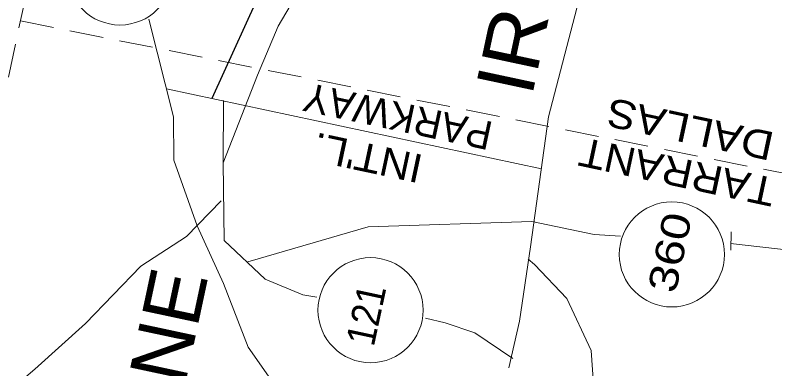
# Model space of a CAD drawing. Extents: x 2363411 to 2369126, y 6976878 to 6988319.
# Drawn here: x 2365843.9 to 2365979.2, y 6977238.8 to 6977301.9 of the extents above; entities that cross this region are included whole.
import ezdxf

# ---------------------------------------------------------------- set-up
doc = ezdxf.new("R2010")
doc.units = 0
doc.header["$LTSCALE"] = 2
doc.linetypes.add('MEDIUM_DASHED', pattern=[4.5, 3, -1.5])
doc.layers.add('62', color=7, linetype='Continuous', lineweight=13)
doc.layers.add('63', color=7, linetype='Continuous', lineweight=13)

msp = doc.modelspace()

# ---------------------------------------------------------------- linework, layer by layer
at = {"layer": '62', "linetype": 'MEDIUM_DASHED'}
for p, q in [((2365864.629, 6977393.47), (2365770.962, 6976955.102)), ((2365844.834, 6977300.827), (2366120.392, 6977245.768))]:
    msp.add_line(p, q, dxfattribs=at)
at = {"layer": '62'}
for p, q in [((2365937.638, 6977274.464), (2365870.829, 6977288.739)), ((2365880.938, 6977275.533), (2365880.992, 6977286.661)), ((2365874.425, 6977262.384), (2365880.614, 6977268.745)), ((2365935.934, 6977265.095), (2365947.026, 6977262.727)), ((2365947.026, 6977262.727), (2365951.756, 6977262.473)), ((2365971.404, 6977259.979), (2365971.456, 6977263.236)), ((2365983.687, 6977259.747), (2365971.313, 6977261.17)), ((2365936.413, 6977257.422), (2365935.278, 6977258.356)), ((2365895.124, 6977252.002), (2365897.618, 6977251.608)), ((2365920.523, 6977247.035), (2365916.971, 6977247.863)), ((2365933.745, 6977247.316), (2365931.81, 6977239.009)), ((2365885.393, 6977242.646), (2365892.097, 6977233.203))]:
    msp.add_line(p, q, dxfattribs=at)
for points in [[(2365933.745, 6977247.316), (2365935.719, 6977260.537), (2365938.925, 6977283.713), (2365944.32, 6977304.446), (2365947.999, 6977318.223), (2365951.965, 6977335.808), (2365951.701, 6977346.428), (2365947.185, 6977359.539), (2365943.374, 6977373.908), (2365943.087, 6977378.064)], [(2365887.078, 6977291.135), (2365890.75, 6977299.923), (2365897.513, 6977311.432), (2365905.681, 6977318.96)], [(2365876.303, 6977264.283), (2365872.175, 6977275.98), (2365872.104, 6977283.724), (2365867.682, 6977301.146)], [(2365881.155, 6977261.684), (2365880.938, 6977275.533), (2365887.078, 6977291.135)], [(2365876.303, 6977264.283), (2365881.03, 6977254), (2365885.393, 6977242.646)], [(2365935.934, 6977265.095), (2365906.78, 6977264.121), (2365885.362, 6977257.908)], [(2365745.602, 6977025.615), (2365742.995, 6977037.011), (2365744.177, 6977051.369), (2365754.758, 6977065.562), (2365757.967, 6977076.059), (2365767.656, 6977087.91), (2365774.215, 6977096.102), (2365778.852, 6977103.376), (2365783.338, 6977114.034), (2365786.122, 6977122.873), (2365789.101, 6977134.663), (2365791.544, 6977148.682), (2365797.575, 6977165.918), (2365800.831, 6977177.279), (2365805.2, 6977190.083), (2365814.728, 6977203.211), (2365824.115, 6977215.605), (2365833.318, 6977226.804), (2365847.376, 6977238.756), (2365856.409, 6977246.882), (2365866.274, 6977257.086), (2365874.425, 6977262.384)], [(2365895.124, 6977252.002), (2365888.401, 6977254.796), (2365881.155, 6977261.684)], [(2365947.455, 6977228.349), (2365946.525, 6977242.078), (2365942.171, 6977251.316), (2365936.413, 6977257.422)], [(2365932.577, 6977240.663), (2365925.797, 6977245.218), (2365920.523, 6977247.035)]]:
    msp.add_lwpolyline(points, dxfattribs=at)
at = {"layer": '62', "lineweight": 25}
msp.add_lwpolyline([(2365903.569, 6977335.148), (2365888.706, 6977308.551), (2365878.926, 6977287.009)], dxfattribs=at)
at = {"layer": '62'}
for centre in [(2365862.565, 6977309.461), (2365960.88, 6977259.201), (2365907.202, 6977249.263)]:
    msp.add_circle(centre, 9.364, dxfattribs=at)
at = {"layer": '63', "linetype": 'MEDIUM_DASHED'}
for p, q in [((2365864.629, 6977393.47), (2365770.962, 6976955.102)), ((2365844.834, 6977300.827), (2366120.392, 6977245.768))]:
    msp.add_line(p, q, dxfattribs=at)
at = {"layer": '63'}
for p, q in [((2365937.638, 6977274.464), (2365870.829, 6977288.739)), ((2365880.938, 6977275.533), (2365880.992, 6977286.661)), ((2365874.425, 6977262.384), (2365880.614, 6977268.745)), ((2365935.934, 6977265.095), (2365947.026, 6977262.727)), ((2365947.026, 6977262.727), (2365951.756, 6977262.473)), ((2365971.404, 6977259.979), (2365971.456, 6977263.236)), ((2365983.687, 6977259.747), (2365971.313, 6977261.17)), ((2365936.413, 6977257.422), (2365935.278, 6977258.356)), ((2365895.124, 6977252.002), (2365897.618, 6977251.608)), ((2365920.523, 6977247.035), (2365916.971, 6977247.863)), ((2365933.745, 6977247.316), (2365931.81, 6977239.009)), ((2365885.393, 6977242.646), (2365892.097, 6977233.203))]:
    msp.add_line(p, q, dxfattribs=at)
for points in [[(2365933.745, 6977247.316), (2365935.719, 6977260.537), (2365938.925, 6977283.713), (2365944.32, 6977304.446), (2365947.999, 6977318.223), (2365951.965, 6977335.808), (2365951.701, 6977346.428), (2365947.185, 6977359.539), (2365943.374, 6977373.908), (2365943.087, 6977378.064)], [(2365887.078, 6977291.135), (2365890.75, 6977299.923), (2365897.513, 6977311.432), (2365905.681, 6977318.96)], [(2365876.303, 6977264.283), (2365872.175, 6977275.98), (2365872.104, 6977283.724), (2365867.682, 6977301.146)], [(2365881.155, 6977261.684), (2365880.938, 6977275.533), (2365887.078, 6977291.135)], [(2365876.303, 6977264.283), (2365881.03, 6977254), (2365885.393, 6977242.646)], [(2365935.934, 6977265.095), (2365906.78, 6977264.121), (2365885.362, 6977257.908)], [(2365745.602, 6977025.615), (2365742.995, 6977037.011), (2365744.177, 6977051.369), (2365754.758, 6977065.562), (2365757.967, 6977076.059), (2365767.656, 6977087.91), (2365774.215, 6977096.102), (2365778.852, 6977103.376), (2365783.338, 6977114.034), (2365786.122, 6977122.873), (2365789.101, 6977134.663), (2365791.544, 6977148.682), (2365797.575, 6977165.918), (2365800.831, 6977177.279), (2365805.2, 6977190.083), (2365814.728, 6977203.211), (2365824.115, 6977215.605), (2365833.318, 6977226.804), (2365847.376, 6977238.756), (2365856.409, 6977246.882), (2365866.274, 6977257.086), (2365874.425, 6977262.384)], [(2365895.124, 6977252.002), (2365888.401, 6977254.796), (2365881.155, 6977261.684)], [(2365947.455, 6977228.349), (2365946.525, 6977242.078), (2365942.171, 6977251.316), (2365936.413, 6977257.422)], [(2365932.577, 6977240.663), (2365925.797, 6977245.218), (2365920.523, 6977247.035)]]:
    msp.add_lwpolyline(points, dxfattribs=at)
at = {"layer": '63', "lineweight": 25}
msp.add_lwpolyline([(2365903.569, 6977335.148), (2365888.706, 6977308.551), (2365878.926, 6977287.009)], dxfattribs=at)
at = {"layer": '63'}
for centre in [(2365862.565, 6977309.461), (2365960.88, 6977259.201), (2365907.202, 6977249.263)]:
    msp.add_circle(centre, 9.364, dxfattribs=at)

# ---------------------------------------------------------------- texts
at = {"layer": '62'}
for s, height, rotation, width, p in [('IRVING', 10.21, 77.939, 1.1, (2365935.924, 6977287.117)), ('DALLAS', 5.099, 167.939, 1.15, (2365979.388, 6977280.87)), ("INT'L.", 5.099, 167.939, 1.1, (2365916.842, 6977276.862)), ('TARRANT', 5.099, 167.939, 1.1, (2365979.686, 6977272.683)), ('360', 5.099, 77.939, 1.25, (2365961.526, 6977252.08)), ('GRAPEVINE', 10.21, 77.939, 1.05, (2365860.825, 6977173.432)), ('121', 5.099, 77.939, 0.95, (2365907.773, 6977242.605))]:
    msp.add_text(s, height=height, rotation=rotation, dxfattribs=dict(at, width=width)).set_placement(p)
msp.add_text('PARKWAY', height=5.099, rotation=167.939, dxfattribs=at).set_placement((2365929.257, 6977282.744))
at = {"layer": '63'}
for s, height, rotation, width, p in [('IRVING', 10.21, 77.939, 1.1, (2365935.924, 6977287.117)), ('DALLAS', 5.099, 167.939, 1.15, (2365979.388, 6977280.87)), ("INT'L.", 5.099, 167.939, 1.1, (2365916.842, 6977276.862)), ('TARRANT', 5.099, 167.939, 1.1, (2365979.686, 6977272.683)), ('360', 5.099, 77.939, 1.25, (2365961.526, 6977252.08)), ('GRAPEVINE', 10.21, 77.939, 1.05, (2365860.825, 6977173.432)), ('121', 5.099, 77.939, 0.95, (2365907.773, 6977242.605))]:
    msp.add_text(s, height=height, rotation=rotation, dxfattribs=dict(at, width=width)).set_placement(p)
msp.add_text('PARKWAY', height=5.099, rotation=167.939, dxfattribs=at).set_placement((2365929.257, 6977282.744))

doc.saveas('drawing.dxf')
